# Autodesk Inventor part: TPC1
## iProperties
Shininess: 64.0
Length Units: 11272
Angle Units: 11279
Time Units: 11290
Mass Units: 11286
Length Display Precision: 3
Angle Display Precision: 2
Compacted: True
Part Number: TPC1
Document SubType Name: Modeling
Created: 2004-08
Designer: Lori
Manufacturer: Standard
Standards Organization: Custom
Material: Delrin, White
Density: 0.0
Volumn: 0.0
Area: 0.0
PropertySet Name: Model Information
Control State: 0
Master: False
Checked Out: False
Author: Lori
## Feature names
1. Base1
